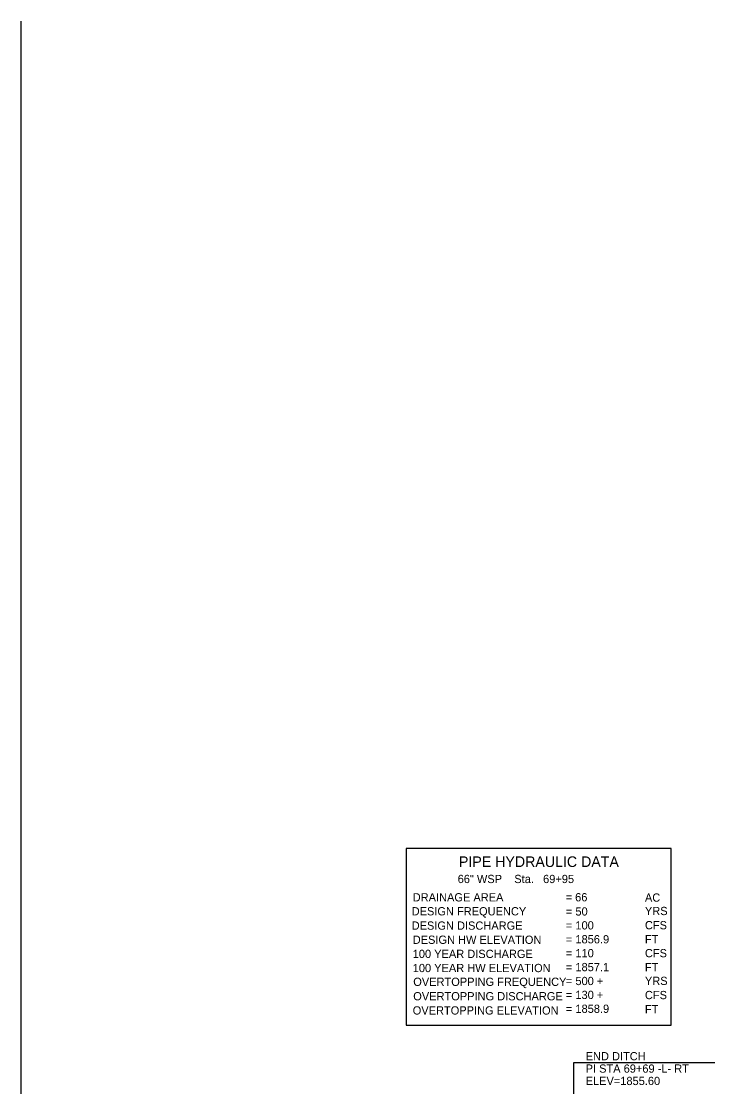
# Model space of a CAD drawing. Extents: x 1025306 to 1036906, y 638983 to 643947.
# Drawn here: x 1030806 to 1031394, y 641847 to 642751 of the extents above; entities that cross this region are included whole.
import ezdxf

# ---------------------------------------------------------------- set-up
doc = ezdxf.new("R2010")
doc.units = 0
for name, color, linetype in [('Prop PFL Pipe Hydraulic Data CELL', 7, 'Continuous'), ('Prop VPI Ditch Grade Right Label', 7, 'Continuous'), ('Scratch_Level_3', 7, 'Continuous')]:
    doc.layers.add(name, color=color, linetype=linetype)

msp = doc.modelspace()

# ---------------------------------------------------------------- linework, layer by layer
at = {"layer": 'Prop PFL Pipe Hydraulic Data CELL'}
msp.add_lwpolyline([(1031132.25, 641898.86), (1031357.25, 641898.86), (1031357.25, 642048.86), (1031132.25, 642048.86)], close=True, dxfattribs=at)
at = {"layer": 'Prop VPI Ditch Grade Right Label'}
msp.add_lwpolyline([(1031274.6, 641767.44), (1031274.6, 641867.3), (1031394.13, 641867.3)], dxfattribs=at)
at = {"layer": 'Scratch_Level_3'}
msp.add_line((1030805.6, 639889.44), (1030805.6, 642751.03), dxfattribs=at)

# ---------------------------------------------------------------- texts
at = {"layer": 'Prop PFL Pipe Hydraulic Data CELL'}
for s, height, p in [('PIPE HYDRAULIC DATA', 8.9997, (1031177.05, 642033.21)), ('  66" WSP    Sta.   69+95  ', 6.9996, (1031170.78, 642019.54)), ('DRAINAGE AREA', 6.9999, (1031137.82, 642003.96)), ('= 66  ', 7, (1031267.61, 642004.04)), ('AC', 7, (1031334.91, 642003.76)), ('DESIGN FREQUENCY', 6.9999, (1031136.92, 641992.11)), ('= 50 ', 7, (1031267.85, 641991.96)), ('YRS', 7, (1031334.91, 641992.36)), ('DESIGN DISCHARGE', 6.9999, (1031136.92, 641979.96)), ('= 100', 7, (1031267.85, 641980.16)), ('CFS', 7, (1031334.91, 641980.31)), ('DESIGN HW ELEVATION', 6.9999, (1031137.82, 641967.96)), ('= 1856.9', 7, (1031267.85, 641968.36)), ('FT', 7, (1031334.91, 641968.36)), ('100 YEAR DISCHARGE', 6.9999, (1031137.82, 641955.96)), ('= 110', 7, (1031267.85, 641956.56)), ('CFS', 7, (1031334.91, 641956.56)), ('100 YEAR HW ELEVATION', 6.9999, (1031137.82, 641943.96)), ('= 1857.1', 7, (1031267.85, 641944.76)), ('FT', 7, (1031334.91, 641944.76)), ('OVERTOPPING FREQUENCY', 6.9999, (1031138.27, 641932.26)), ('= 500 +  ', 7, (1031267.85, 641932.96)), ('YRS', 7, (1031334.91, 641933.06)), ('OVERTOPPING DISCHARGE', 6.9999, (1031138.27, 641920.01)), ('= 130 +  ', 7, (1031267.85, 641921.16)), ('CFS', 7, (1031334.91, 641921.01)), ('= 1858.9', 7, (1031267.85, 641909.36)), ('OVERTOPPING ELEVATION', 6.9999, (1031137.82, 641907.96)), ('FT', 7, (1031334.91, 641908.96))]:
    msp.add_text(s, height=height, dxfattribs=at).set_placement(p)
at = {"layer": 'Prop VPI Ditch Grade Right Label'}
for s, p in [('END DITCH', (1031284.6, 641869.1)), ('PI STA 69+69 -L- RT', (1031284.6, 641858.6)), ('ELEV=1855.60', (1031284.6, 641848.1))]:
    msp.add_text(s, height=7, dxfattribs=at).set_placement(p)

doc.saveas('drawing.dxf')
